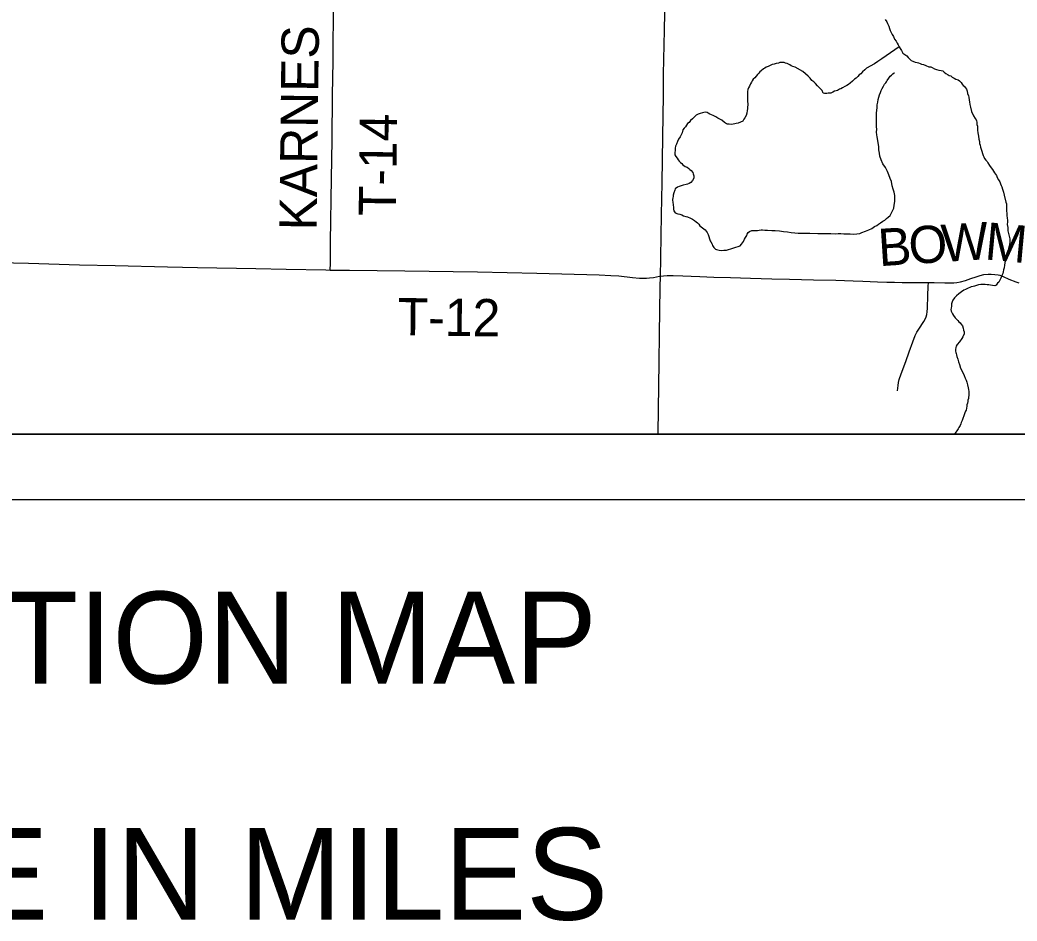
# Model space of a CAD drawing. Extents: x 0 to 34, y 0 to 22.
# Drawn here: x 26.787 to 28.306, y 13.358 to 14.731 of the extents above; entities that cross this region are included whole.
import ezdxf

# ---------------------------------------------------------------- set-up
doc = ezdxf.new("R2010")
doc.units = 0
for name, color, linetype in [('GM_X_Minor_River', 7, 'Continuous'), ('GM_X_State_Route', 7, 'Continuous'), ('GM_X_Township_Road', 7, 'Continuous'), ('GM_X_Township_Road_Text', 7, 'Continuous'), ('SH_Data', 7, 'Continuous'), ('SH_Text', 7, 'Continuous')]:
    doc.layers.add(name, color=color, linetype=linetype)

msp = doc.modelspace()

# ---------------------------------------------------------------- linework, layer by layer
at = {"layer": 'GM_X_Minor_River'}
for points in [[(28.105, 14.7319), (28.1076, 14.7285), (28.109, 14.7261), (28.1108, 14.7219), (28.1119, 14.7181), (28.113, 14.715), (28.1145, 14.7123), (28.1159, 14.7092), (28.1177, 14.7058), (28.1196, 14.7019), (28.1218, 14.6988), (28.1236, 14.6961), (28.1251, 14.6934), (28.1266, 14.6903), (28.128, 14.6876), (28.1299, 14.6846), (28.1324, 14.6807), (28.1381, 14.6768), (28.1403, 14.674), (28.1429, 14.6713), (28.1451, 14.6694), (28.1474, 14.6686), (28.1512, 14.667), (28.1538, 14.6665), (28.1561, 14.6661), (28.1584, 14.6649), (28.1606, 14.6641), (28.1637, 14.6633), (28.1671, 14.6617), (28.1716, 14.66), (28.175, 14.6596), (28.1769, 14.6588), (28.1803, 14.6568), (28.1837, 14.6556), (28.1871, 14.6547), (28.1905, 14.6543), (28.1932, 14.6538), (28.1954, 14.6519), (28.1976, 14.6496), (28.201, 14.6476), (28.2029, 14.6468), (28.2052, 14.646), (28.2071, 14.644), (28.2104, 14.6424), (28.2131, 14.6412), (28.2165, 14.64), (28.2187, 14.6384), (28.221, 14.6357), (28.2228, 14.6334), (28.2239, 14.6315), (28.2258, 14.6303), (28.2276, 14.6276), (28.2291, 14.6256), (28.2302, 14.6226), (28.2309, 14.6191), (28.232, 14.6157), (28.2327, 14.6134), (28.2333, 14.6088), (28.2337, 14.6065), (28.2343, 14.6023), (28.2354, 14.5985), (28.2368, 14.592), (28.2397, 14.585), (28.2423, 14.5812), (28.2441, 14.5792), (28.2445, 14.5773), (28.2448, 14.5754), (28.2451, 14.572), (28.2458, 14.5693), (28.2462, 14.5674), (28.2461, 14.5651), (28.2461, 14.5632), (28.2467, 14.559), (28.2474, 14.5544), (28.2481, 14.5498), (28.2488, 14.546), (28.2491, 14.543), (28.2498, 14.5403), (28.2505, 14.5376), (28.2515, 14.5341), (28.2526, 14.5315), (28.2537, 14.5276), (28.2548, 14.5246), (28.2555, 14.5226), (28.2566, 14.5203), (28.2588, 14.5176), (28.2607, 14.5157), (28.2618, 14.5134), (28.264, 14.5095), (28.2669, 14.506), (28.2688, 14.5033), (28.2702, 14.5006), (28.2717, 14.4983), (28.2736, 14.496), (28.2751, 14.494), (28.2761, 14.491), (28.278, 14.4875), (28.2798, 14.4844), (28.2809, 14.4817)], [(28.1266, 14.6903), (28.0999, 14.6719), (28.0941, 14.6678), (28.0891, 14.6645), (28.0767, 14.6576), (28.074, 14.655), (28.0709, 14.652), (28.0682, 14.6494), (28.0658, 14.6475), (28.0635, 14.6453), (28.0612, 14.6427), (28.0585, 14.6408), (28.0557, 14.6379), (28.0519, 14.6349), (28.0492, 14.6331), (28.0469, 14.6316), (28.0438, 14.6297), (28.0403, 14.6279), (28.0376, 14.6265), (28.0357, 14.6257), (28.0326, 14.6239), (28.0307, 14.6232), (28.028, 14.6225), (28.0253, 14.621), (28.0226, 14.6199), (28.0203, 14.6196), (28.0184, 14.6196), (28.0165, 14.6193), (28.0146, 14.6194), (28.0127, 14.6194), (28.0108, 14.6198), (28.009, 14.6237), (28.0053, 14.6279), (28.0019, 14.6311), (27.9989, 14.6342), (27.9963, 14.6369), (27.9937, 14.6392), (27.9911, 14.6423), (27.9881, 14.6458), (27.984, 14.6493), (27.9799, 14.6525), (27.9679, 14.6592), (27.9645, 14.6604), (27.9622, 14.6616), (27.9599, 14.6628), (27.9581, 14.664), (27.9558, 14.6648), (27.9535, 14.6656), (27.9513, 14.6664), (27.949, 14.6665), (27.9467, 14.6662), (27.9448, 14.6662), (27.9425, 14.6655), (27.939, 14.6648), (27.936, 14.6641), (27.9329, 14.6634), (27.9298, 14.662), (27.9268, 14.6605), (27.9241, 14.6594), (27.9217, 14.658), (27.9198, 14.6569), (27.9163, 14.6535), (27.9144, 14.652), (27.9128, 14.6502), (27.9109, 14.6483), (27.9085, 14.6457), (27.9066, 14.6431), (27.9042, 14.6408), (27.9027, 14.6386), (27.9015, 14.6367), (27.8999, 14.6341), (27.8983, 14.6303), (27.8967, 14.6277), (27.8959, 14.6254), (27.8955, 14.622), (27.8954, 14.6182), (27.8953, 14.6148), (27.8953, 14.6121), (27.8952, 14.6091), (27.8955, 14.6064), (27.8958, 14.6041), (27.8958, 14.6014), (27.8954, 14.5988), (27.8953, 14.5957), (27.8948, 14.5931), (27.8944, 14.5893), (27.8932, 14.5855), (27.8916, 14.5821), (27.89, 14.5799), (27.8884, 14.5772), (27.885, 14.5754), (27.8811, 14.574), (27.8781, 14.5733), (27.8761, 14.5729), (27.8738, 14.5722), (27.8704, 14.5719), (27.8674, 14.5724), (27.8651, 14.5724), (27.8632, 14.5732)], [(28.0956, 14.6134), (28.0964, 14.6172), (28.098, 14.6209), (28.0992, 14.6236), (28.1008, 14.627), (28.1028, 14.6303), (28.1044, 14.6333), (28.106, 14.6352), (28.1071, 14.6371), (28.1083, 14.639), (28.1107, 14.6423), (28.113, 14.6457), (28.115, 14.6472), (28.1169, 14.6491), (28.1192, 14.6509), (28.1196, 14.6509)], [(27.8484, 14.3813), (27.8503, 14.3809), (27.8522, 14.3804), (27.8556, 14.38), (27.8595, 14.3803), (27.8633, 14.3806), (27.8667, 14.3816), (27.8702, 14.3827), (27.8748, 14.3841), (27.8844, 14.387), (27.8863, 14.3896), (27.8879, 14.3915), (27.8895, 14.3937), (27.8907, 14.3971), (27.8926, 14.3997), (27.8942, 14.4027), (27.895, 14.405), (27.8966, 14.4073), (27.8985, 14.4091), (27.902, 14.4102), (27.9066, 14.4105), (27.9108, 14.4104), (27.913, 14.4107), (27.9161, 14.4114), (27.9184, 14.4113), (27.9218, 14.4109), (27.926, 14.4108), (27.9325, 14.4106), (27.9378, 14.4105), (27.9443, 14.41), (27.9503, 14.4091), (27.9564, 14.4082), (27.9621, 14.4073), (27.9674, 14.4068), (27.9724, 14.4063), (27.9773, 14.4062), (27.9834, 14.4061), (27.9903, 14.4063), (28.0028, 14.406), (28.0131, 14.4058), (28.0226, 14.406), (28.0295, 14.4054), (28.0337, 14.4057), (28.0378, 14.4056), (28.0424, 14.4055), (28.0466, 14.4054), (28.05, 14.4054), (28.0519, 14.4053), (28.0572, 14.4048), (28.0622, 14.4051), (28.0668, 14.4058), (28.0699, 14.4072), (28.0752, 14.4094), (28.0802, 14.4116), (28.0848, 14.4137), (28.0891, 14.4163), (28.0926, 14.4181), (28.0953, 14.42), (28.098, 14.4222), (28.1015, 14.4248), (28.1049, 14.4262), (28.1072, 14.4285), (28.11, 14.4307), (28.1127, 14.4333), (28.1143, 14.4363), (28.1163, 14.4405), (28.1183, 14.4446), (28.1191, 14.4491), (28.12, 14.4548), (28.1201, 14.4594), (28.1198, 14.4636), (28.1191, 14.4686), (28.1173, 14.4735), (28.1159, 14.4785), (28.1149, 14.485), (28.1131, 14.4896), (28.111, 14.495), (28.1088, 14.5004), (28.1059, 14.5062), (28.1018, 14.512), (28.0989, 14.5181), (28.0971, 14.5235), (28.0964, 14.5285), (28.0958, 14.5334), (28.0955, 14.5384), (28.0928, 14.5529), (28.0925, 14.5563), (28.0922, 14.5605), (28.0923, 14.5647), (28.092, 14.5685), (28.092, 14.5723), (28.0921, 14.5769), (28.0922, 14.5815), (28.0919, 14.5853), (28.092, 14.5891), (28.0925, 14.594), (28.093, 14.5974), (28.0931, 14.602), (28.0939, 14.6062), (28.0947, 14.61), (28.0956, 14.6134)], [(27.8632, 14.5732), (27.8602, 14.5752), (27.8561, 14.5783), (27.8534, 14.5799), (27.8501, 14.5815), (27.8474, 14.5835), (27.8433, 14.5855), (27.8403, 14.5867), (27.838, 14.5879), (27.8357, 14.5891), (27.8339, 14.5902), (27.8308, 14.5907), (27.8266, 14.5896), (27.8235, 14.5886), (27.8201, 14.5875), (27.8174, 14.5864), (27.8139, 14.5831), (27.8116, 14.5805), (27.8088, 14.5778), (27.8065, 14.5752), (27.8042, 14.5734), (27.8026, 14.5711), (27.801, 14.5685), (27.7991, 14.5663), (27.7971, 14.5636), (27.7959, 14.5591), (27.7927, 14.5531), (27.7903, 14.5497), (27.7887, 14.5459), (27.7871, 14.5418), (27.7859, 14.5388), (27.7851, 14.5357), (27.7849, 14.5258), (27.786, 14.5232), (27.7882, 14.5204), (27.7897, 14.5181), (27.7915, 14.5162), (27.7934, 14.5142), (27.7953, 14.5123), (27.7971, 14.5107), (27.8005, 14.508), (27.8035, 14.5068), (27.8058, 14.5048), (27.8076, 14.5033), (27.8095, 14.5017), (27.8121, 14.4986), (27.8128, 14.4967), (27.8135, 14.4936), (27.8134, 14.4902), (27.8118, 14.4864), (27.8091, 14.4838), (27.8064, 14.482), (27.8041, 14.4809), (27.8018, 14.4805), (27.7976, 14.4795), (27.7942, 14.4784), (27.7915, 14.4777), (27.7888, 14.4763), (27.7853, 14.4741), (27.7845, 14.4718), (27.7833, 14.4676), (27.782, 14.4642), (27.782, 14.4623), (27.7816, 14.4601), (27.7811, 14.4578), (27.7818, 14.4524), (27.7821, 14.4505), (27.7821, 14.4486), (27.7824, 14.4463), (27.7827, 14.4429), (27.7834, 14.4402), (27.7853, 14.4375), (27.7891, 14.4359), (27.7921, 14.4351), (27.7955, 14.4342), (27.7981, 14.433), (27.8012, 14.4318), (27.8038, 14.431), (27.8083, 14.4294), (27.8117, 14.4278), (27.8147, 14.4258), (27.8174, 14.4235), (27.8192, 14.4219), (27.8211, 14.42), (27.8229, 14.4176), (27.8248, 14.4161), (27.8267, 14.4145), (27.8289, 14.4129), (27.8308, 14.4114), (27.8323, 14.4094), (27.8341, 14.4071), (27.8356, 14.4044), (27.8367, 14.4013), (27.8377, 14.3975), (27.8384, 14.3948), (27.8396, 14.3929), (27.8414, 14.3894), (27.8421, 14.3875), (27.8443, 14.3844), (27.8466, 14.3821), (27.8484, 14.3813)], [(28.2809, 14.4817), (28.282, 14.479), (28.2831, 14.4767), (28.2841, 14.4733), (28.2856, 14.4687), (28.2866, 14.4641), (28.289, 14.4534), (28.2901, 14.4511), (28.2901, 14.4488), (28.2904, 14.4465), (28.2904, 14.4434), (28.2903, 14.44), (28.2906, 14.437), (28.2905, 14.4332), (28.2912, 14.4293), (28.2915, 14.4263), (28.2915, 14.4236), (28.2914, 14.4194), (28.292, 14.4149), (28.2923, 14.4099), (28.2934, 14.4057), (28.2944, 14.4019), (28.2951, 14.3977), (28.2954, 14.3954), (28.2954, 14.3927), (28.2949, 14.3897), (28.2941, 14.3863), (28.2932, 14.3828), (28.2928, 14.3798), (28.292, 14.3756), (28.2904, 14.3722), (28.2895, 14.3688), (28.2883, 14.3658), (28.2879, 14.3635), (28.2874, 14.3609), (28.287, 14.3575), (28.2865, 14.3537), (28.2857, 14.3503), (28.2853, 14.3472), (28.2844, 14.345), (28.2836, 14.3427), (28.2824, 14.3404), (28.2816, 14.3378), (28.2804, 14.3355), (28.2796, 14.3337), (28.2784, 14.3318), (28.2765, 14.3299), (28.2742, 14.3273), (28.2722, 14.3262), (28.2688, 14.3267), (28.2658, 14.3271), (28.2631, 14.3276), (28.2605, 14.3276), (28.2574, 14.3281), (28.2548, 14.3281), (28.251, 14.3282), (28.2475, 14.3275), (28.2444, 14.3264), (28.2414, 14.3257), (28.2391, 14.325), (28.2364, 14.3243), (28.2341, 14.3236), (28.2318, 14.3225), (28.2295, 14.3214), (28.2276, 14.3203), (28.2249, 14.3193), (28.2218, 14.3167), (28.2175, 14.3141), (28.214, 14.3107), (28.2109, 14.3078), (28.2086, 14.3044), (28.2074, 14.3018), (28.2065, 14.2987), (28.2061, 14.2953), (28.2056, 14.2919), (28.2052, 14.29), (28.2059, 14.2873), (28.2066, 14.2854), (28.2081, 14.2835), (28.2096, 14.2808), (28.2118, 14.2773), (28.214, 14.2753), (28.2159, 14.273), (28.2177, 14.2711), (28.2196, 14.2699), (28.2207, 14.268), (28.2229, 14.2649), (28.224, 14.2618), (28.2247, 14.2584), (28.2254, 14.2561), (28.2254, 14.253), (28.2237, 14.2485), (28.2222, 14.2458), (28.2186, 14.2406), (28.2151, 14.2369), (28.2132, 14.2342), (28.2127, 14.232), (28.2123, 14.2293), (28.2122, 14.2267), (28.2129, 14.2247), (28.2133, 14.2228)], [(28.2133, 14.2228), (28.214, 14.2209), (28.2147, 14.2186), (28.2158, 14.2144), (28.2172, 14.2102), (28.2183, 14.2063), (28.2201, 14.2006), (28.223, 14.1948), (28.2255, 14.1894), (28.2273, 14.1852), (28.2288, 14.1821), (28.2295, 14.1791), (28.2306, 14.1752), (28.2316, 14.1706), (28.2323, 14.168), (28.2326, 14.1649), (28.2329, 14.1615), (28.2329, 14.1588), (28.2324, 14.1565), (28.232, 14.1543), (28.2312, 14.152), (28.2311, 14.1497), (28.2307, 14.1471), (28.2299, 14.1448), (28.2299, 14.1425), (28.2294, 14.1395), (28.2286, 14.1368), (28.2278, 14.1349), (28.2266, 14.1327), (28.2262, 14.1308), (28.225, 14.1278), (28.2237, 14.124), (28.2225, 14.1206), (28.2213, 14.118), (28.2205, 14.1157), (28.2193, 14.1134), (28.2177, 14.1104), (28.2166, 14.1082), (28.211, 14.1)]]:
    msp.add_lwpolyline(points, dxfattribs=at)
at = {"layer": 'GM_X_State_Route'}
for points in [[(27.7633, 14.3694), (27.7643, 14.4345), (27.7652, 14.483), (27.7663, 14.5533), (27.7673, 14.6167), (27.7676, 14.6484), (27.7688, 14.7155), (27.7693, 14.7416), (27.7696, 14.7677), (27.7705, 14.8199), (27.7712, 14.8703), (27.7718, 14.9113), (27.7724, 14.9567), (27.7731, 15.0014), (27.7735, 15.0294), (27.7738, 15.0561), (27.7745, 15.0797), (27.7751, 15.1201), (27.7758, 15.1537), (27.7766, 15.1866), (27.7773, 15.2243)], [(27.759, 14.1), (27.7591, 14.1014), (27.7609, 14.2095), (27.7615, 14.2524), (27.7625, 14.3239), (27.7628, 14.3408), (27.7632, 14.3674), (27.7633, 14.3694)]]:
    msp.add_lwpolyline(points, dxfattribs=at)
at = {"layer": 'GM_X_Township_Road'}
for points in [[(23.5167, 18.4074), (23.5167, 14.1), (28.7673, 14.1), (28.7709, 14.3107), (28.7934, 15.3155), (28.8021, 16.3696)], [(27.2595, 14.3502), (27.2596, 14.3541), (27.2597, 14.3566), (27.26, 14.3933), (27.2614, 14.4896), (27.2622, 14.5481), (27.263, 14.6165), (27.2637, 14.6687), (27.2647, 14.7601), (27.2655, 14.816), (27.2663, 14.9105), (27.2667, 14.9553), (27.267, 14.9944), (27.2674, 15.0442), (27.2678, 15.079), (27.2682, 15.1219), (27.2685, 15.1536), (27.2688, 15.1915), (27.269, 15.212), (27.2694, 15.253), (27.27, 15.3598)], [(26.7567, 14.3615), (26.7765, 14.3611), (26.7995, 14.3604), (26.8772, 14.3583), (26.9319, 14.3569), (27.0114, 14.3549), (27.0574, 14.354), (27.1463, 14.3523), (27.1923, 14.3514), (27.2526, 14.3503), (27.2595, 14.3502)], [(27.2595, 14.3502), (27.2887, 14.3499), (27.3732, 14.3489), (27.4839, 14.3474), (27.5746, 14.3453), (27.6691, 14.3427), (27.687, 14.342), (27.6994, 14.3411), (27.7204, 14.3388), (27.731, 14.338), (27.7372, 14.3378), (27.7416, 14.3379), (27.746, 14.3382), (27.7522, 14.339), (27.7614, 14.3406), (27.7628, 14.3408)], [(27.7628, 14.3408), (27.7675, 14.3415), (27.773, 14.3418), (27.7823, 14.3417), (27.7971, 14.3411), (27.8096, 14.3406), (27.8226, 14.3401), (27.8443, 14.3395), (27.8697, 14.3387), (27.8846, 14.3382), (27.9002, 14.3377), (27.9325, 14.3369), (27.9592, 14.3364), (27.9959, 14.3353), (28.0299, 14.3345), (28.0567, 14.3338), (28.0712, 14.3332), (28.0934, 14.3324), (28.1077, 14.3319), (28.1195, 14.3315), (28.1313, 14.3314), (28.1493, 14.3313), (28.1648, 14.3313), (28.1711, 14.3313)], [(28.1242, 14.166), (28.1249, 14.174), (28.1256, 14.1789), (28.1266, 14.1832), (28.1295, 14.192), (28.1365, 14.2106), (28.1417, 14.2253), (28.1472, 14.2405), (28.1511, 14.2503), (28.1535, 14.2553), (28.1563, 14.2601), (28.164, 14.2715), (28.1661, 14.2753), (28.1675, 14.2787), (28.1685, 14.2823), (28.1692, 14.2866), (28.1697, 14.2921), (28.1701, 14.3114), (28.1708, 14.3251), (28.1711, 14.3313)], [(28.1711, 14.3313), (28.18, 14.3312), (28.1962, 14.3309), (28.205, 14.3309), (28.2101, 14.3309), (28.2147, 14.3314), (28.2203, 14.3324), (28.2277, 14.3342), (28.236, 14.3371), (28.2438, 14.3398), (28.25, 14.3418), (28.2558, 14.3432), (28.2622, 14.3441), (28.267, 14.3441), (28.2724, 14.3435), (28.2777, 14.3429), (28.2802, 14.3423), (28.2849, 14.3405), (28.2939, 14.3362), (28.3043, 14.3321), (28.3092, 14.3309)]]:
    msp.add_lwpolyline(points, dxfattribs=at)
at = {"layer": 'SH_Data'}
for points in [[(23.4167, 21), (30.4167, 21), (30.4167, 14), (23.4167, 14)], [(23.5167, 20.9), (30.3167, 20.9), (30.3167, 14.1), (23.5167, 14.1)]]:
    msp.add_lwpolyline(points, close=True, dxfattribs=at)

# ---------------------------------------------------------------- texts
at = {"layer": 'GM_X_Township_Road_Text'}
for s, height, rotation, p in [('KARNES', 0.05682, 89.3116, (27.2386, 14.4103)), ('T-14', 0.05682, 89.308, (27.3596, 14.432)), ('W', 0.0568, 3.7002, (28.1926, 14.3623)), ('M', 0.0568, 354.6922, (28.2559, 14.3665)), ('B', 0.0568, 3.7769, (28.0962, 14.3559)), ('O', 0.0568, 3.7748, (28.1427, 14.359)), ('T-12', 0.05682, 359.3043, (27.3621, 14.2508))]:
    msp.add_text(s, height=height, rotation=rotation, dxfattribs=at).set_placement(p)
at = {"layer": 'SH_Text'}
for s, p in [('LOCATION MAP', (26.2513, 13.72)), ('SCALE IN MILES', (26.216, 13.36))]:
    msp.add_text(s, height=0.14, dxfattribs=at).set_placement(p)

doc.saveas('drawing.dxf')
